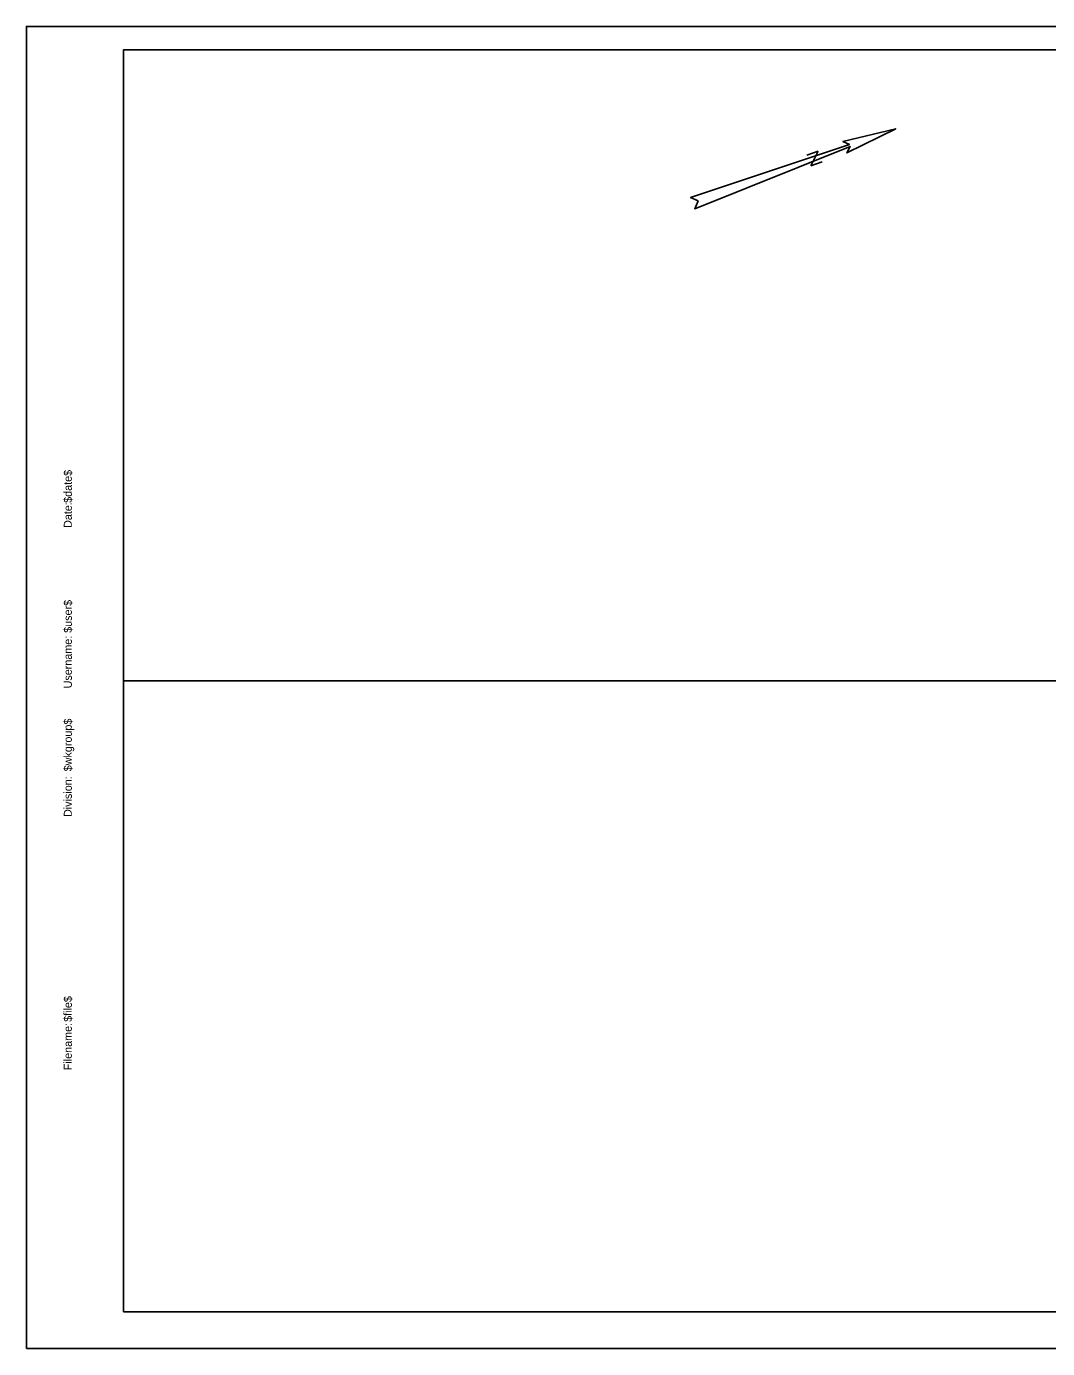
# Model space of a CAD drawing. Extents: x 0 to 850, y 0 to 550.
# Drawn here: x 0 to 425, y 0 to 550 of the extents above; entities that cross this region are included whole.
import ezdxf

# ---------------------------------------------------------------- set-up
doc = ezdxf.new("R2010")
doc.units = 0
for name, color, linetype in [('BORDER', 7, 'Continuous'), ('Default', 7, 'Continuous'), ('H_V CONTROLS', 7, 'Continuous'), ('PLOT BOUNDARY', 7, 'Continuous')]:
    doc.layers.add(name, color=color, linetype=linetype)

msp = doc.modelspace()

# ---------------------------------------------------------------- linework, layer by layer
at = {"layer": 'BORDER'}
for p, q in [((840.33, 540.24), (40.33, 540.24)), ((40.33, 540.24), (40.33, 15.24)), ((40.33, 15.24), (840.33, 15.24))]:
    msp.add_line(p, q, dxfattribs=at)
at = {"layer": 'Default'}
for points in [[(40.33, 15.24), (790.33, 15.24), (790.33, 540.26), (40.33, 540.26)], [(40.33, 540.24), (440.33, 540.24), (440.33, 277.76), (40.33, 277.76)], [(570.96, 277.74), (40.33, 277.74), (40.33, 15.24), (570.96, 15.24)]]:
    msp.add_lwpolyline(points, close=True, dxfattribs=at)
at = {"layer": 'H_V CONTROLS'}
for p, q in [((361.65, 507.42), (339.66, 502.03)), ((361.65, 507.42), (341.38, 497.34)), ((342.37, 500.77), (276.27, 478.84)), ((342.37, 500.77), (339.66, 502.03)), ((342.64, 500.05), (277.99, 474.14)), ((342.64, 500.05), (341.38, 497.34)), ((279.48, 477.35), (276.27, 478.84)), ((279.48, 477.35), (277.99, 474.14))]:
    msp.add_line(p, q, dxfattribs=at)
for points in [[(279.48, 477.35), (277.99, 474.14), (342.64, 500.05), (341.38, 497.34), (361.65, 507.42), (339.66, 502.03), (342.37, 500.77), (276.27, 478.84), (279.48, 477.35)], [(324.68, 496.41), (329.38, 498.13)], [(329.38, 498.13), (326.31, 491.97)], [(326.31, 491.97), (331, 493.69)]]:
    msp.add_lwpolyline(points, dxfattribs=at)
at = {"layer": 'PLOT BOUNDARY'}
msp.add_lwpolyline([(-0.13, -0.05), (849.87, -0.05), (849.87, 549.95), (-0.13, 549.95)], close=True, dxfattribs=at)

# ---------------------------------------------------------------- texts
at = {"layer": 'BORDER'}
for s, p in [('$date$', (18.76, 351.77)), ('Date:', (18.76, 341.33)), ('$user$', (18.76, 297.7)), ('Username:', (18.76, 274.58)), ('$wkgroup$', (18.76, 240.09)), ('Division:', (18.76, 221.08)), ('$file$', (18.76, 135.87)), ('Filename:', (18.76, 115.74))]:
    msp.add_text(s, height=3.348, rotation=90, dxfattribs=at).set_placement(p)

doc.saveas('drawing.dxf')
